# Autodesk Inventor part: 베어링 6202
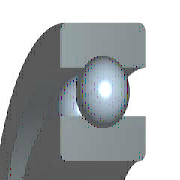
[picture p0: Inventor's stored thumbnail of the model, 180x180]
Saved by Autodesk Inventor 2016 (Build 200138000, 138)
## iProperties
Created: 2012-02
Part Number: 베어링 6202
Material: 강철, 연강
Description: 깊은 그루브 볼 베어링
Document SubType Name: Modeling
Standard: KS B 2023
Designer: mduedu
Standards Organization: KS
Language: ko-KR
Size Designation: 6202 - 15 x 35 x 11
Categories: <MemberInstance><Categories><Category DisplayName="샤프트 부품" InternalName="7f7aeb1f-a693-4053-b835-cee3144e0d98" Mnemonic="SHFT"><Category DisplayName="베어링" Inter
Density: 1 g/cm^3
Appearance: 노란색
IsCustomPart: 1
Author: mduedu
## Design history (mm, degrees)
sketch "스케치" dims "d0" = 5.2 (= -0.26 x WD + 0.26 x BD)
  geometry: L1 (2.9, 12.5)-(8.1, 12.5); L2 (5.5, 12.5)-(5.5, 9.9); L3 (5.5, 12.5)-(5.5, 15.1); L4 (3.568, 10.76)-(0, 10.76); L5 (0, 7.5)-(11, 7.5); L6 (3.568, 14.24)-(0, 14.24); L7 (0, 17.5)-(11, 17.5); L8 (11, 7.5)-(11, 10.76); L9 (7.432, 10.76)-(11, 10.76); L10 (7.432, 14.24)-(11, 14.24); L11 (11, 17.5)-(11, 14.24); L12 (-1.4, 0)-(8.4, 0) reference; L13 (0, -0.3)-(0, 5.3) reference
  constraints: 22 end point, 4 point on line, 2 collinear, 2 perpendicular, 2 symmetric about line, 1 midpoint, 1 parallel, 14 other
  dimensions: "d9" = 15 diameter of L5 L12 (= WD); "d11" = 35 diameter of L7 L12 (= BD); "d12" = 11 distance between parallel lines of L8 L13 (= KB); "d13" = 21.52 diameter of L9 L12 (= 0.326 x BD + 0.674 x WD)
revolve "본체" stored, may be unused: angle "d6" = 90 deg
revolve "볼" stored, may be unused: angle "d7" = 90 deg
pattern_circular "IDS_ARRAYBALL[SIMPL:T]" dims angle "d3" = 360 deg
body "Solid1"
fillet "모깎기1" dims "d1" = 0.6 (= KRS)
other parameters: "WD" = 15 [user parameter; used in 5 equation terms], "BD" = 35 [user parameter; used in 5 equation terms], "KB" = 11 [user parameter; used in 1 equation term], "KRS" = 0.6 [user parameter; used in 1 equation term], "d4" = 0, "d5" = 0, "d8" = 0, "d14" = 0, "d15" = 0, "BBA" = 0 [user parameter], "BC0" = 3750000 [user parameter], "BC" = 7800000 [user parameter], "BR" = 17.5 (= 0.5 x BD) [user parameter], "WR" = 7.5 (= 0.5 x WD) [user parameter]
